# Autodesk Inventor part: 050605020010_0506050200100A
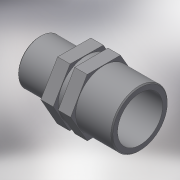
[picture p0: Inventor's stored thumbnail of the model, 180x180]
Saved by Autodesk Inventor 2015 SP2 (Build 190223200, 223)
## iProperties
Created: 2017-05
Part Number: 050605020010_0506050200100A
Material: Generic
Description: PLASSON REDUCING NIPPLE 2"-1"
Document SubType Name: Modeling
Designer: KIM
Density: 1 g/cm^3
Appearance: Default
Author: KIM
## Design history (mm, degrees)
derived "050605.ipt"
feature "Solid1::050605.ipt"
tag "TaggingFeature1"
body "Solid1"
other parameters: "d0" = 61, "d1" = 59.614, "d5" = 25, "d6" = 6.1, "d8" = 0.61, "d12" = 0, "d14" = 33.249, "d15" = 26.5992, "d16" = 47.6912, "d17" = 19, "d18" = 3.05, "d19" = 63, "d21" = 0, "H_" = 61, "R_" = 59.614, "E_" = 63, "l_" = 25, "R_1" = 33.249, "l_1" = 19
